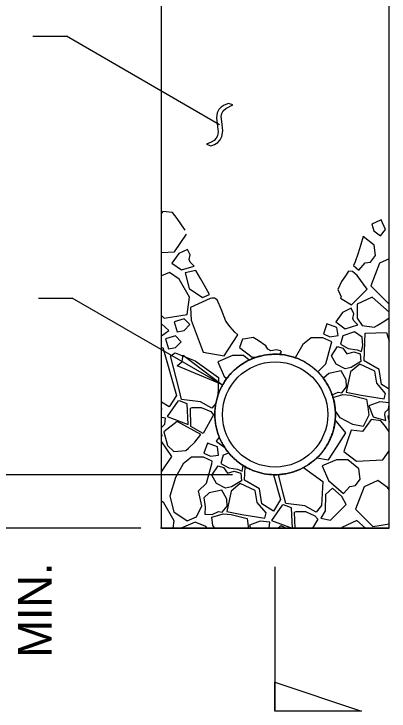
# Model space of a CAD drawing. Extents: x 99862 to 103151, y 100000 to 108153.
# Drawn here: x 100203.1 to 100381.2, y 100207.5 to 100538.8 of the extents above; entities that cross this region are included whole.
import ezdxf

# ---------------------------------------------------------------- set-up
doc = ezdxf.new("R2010")
doc.units = 0
for name, color, linetype in [('Level 10', 7, 'Continuous'), ('Level 14', 7, 'Continuous'), ('Level 15', 7, 'Continuous'), ('Level 2', 7, 'Continuous'), ('Level 20', 7, 'Continuous'), ('Level 9', 7, 'Continuous')]:
    doc.layers.add(name, color=color, linetype=linetype)

msp = doc.modelspace()

# ---------------------------------------------------------------- linework, layer by layer
at = {"layer": 'Level 10'}
for points in [[(100273.15, 100294.34), (100273.15, 100794.33)], [(100381.2, 100294.34), (100381.2, 100794.33)]]:
    msp.add_lwpolyline(points, dxfattribs=at)
at = {"layer": 'Level 14'}
msp.add_line((100329.23, 100376.99), (100330.07, 100378.22), dxfattribs=at)
for points in [[(100284.41, 100436.05), (100280.52, 100441.64), (100278.31, 100444.45), (100273.79, 100444.93), (100273.15, 100444.06)], [(100374.01, 100435.77), (100377.11, 100433.32), (100379.56, 100436.42), (100377.53, 100440.98), (100372.97, 100438.95), (100372.97, 100438.95), (100374.01, 100435.77)], [(100273.15, 100425.51), (100279.29, 100425.8), (100284.95, 100434.08)], [(100368.97, 100433.04), (100367.84, 100429.31), (100367, 100426.71), (100366.48, 100425.11), (100365.04, 100420.99), (100364.36, 100419.22)], [(100364.36, 100419.22), (100366.87, 100417.05), (100369.81, 100420.45), (100372.46, 100420.83), (100374.76, 100423.95), (100374.1, 100428.87), (100368.97, 100433.04)], [(100381.2, 100422.36), (100376.6, 100420.29), (100372.5, 100409.62), (100380.71, 100401.4), (100381.2, 100401.48)], [(100273.15, 100395.48), (100274.49, 100394.14), (100278.43, 100394.79), (100285.28, 100395.94), (100286.48, 100404.16), (100281.55, 100412.7), (100276.95, 100415.98), (100273.15, 100414.27)], [(100295.98, 100405.42), (100293.49, 100409.8), (100291.64, 100413.07), (100289.47, 100416.9), (100284.37, 100415.79), (100286.26, 100408.31), (100292.67, 100404.04), (100295.88, 100405.44)], [(100363.78, 100416.38), (100361.91, 100416.6), (100360.23, 100413.93), (100358.55, 100411.59), (100356.86, 100407.8), (100358.43, 100404.31), (100358.09, 100403.66)], [(100358.09, 100403.66), (100363.38, 100400.52), (100370.75, 100407.97), (100366.06, 100414.44), (100363.78, 100416.38)], [(100297.07, 100403.75), (100296.33, 100403.5), (100286.89, 100399.31), (100287.22, 100393.23), (100292.88, 100378.04), (100302.98, 100376.32), (100307.09, 100382.72), (100309.37, 100386.27)], [(100309.37, 100386.27), (100307.99, 100387.61), (100305.79, 100390.07), (100303.65, 100392.76), (100301.57, 100398.15), (100299.57, 100402.87), (100298.39, 100403.77), (100297.07, 100403.75)], [(100381.2, 100397.11), (100373.2, 100404.2), (100366.03, 100400.88), (100366.1, 100394.16), (100368.47, 100390.78), (100374.18, 100389.95), (100375.57, 100390.68), (100379.13, 100392.88), (100381.2, 100394.43)], [(100283.85, 100388.39), (100286.64, 100391.18), (100283.85, 100393.97), (100279.09, 100392.5), (100280.57, 100387.73), (100280.57, 100387.73), (100283.85, 100388.39)], [(100273.15, 100385.8), (100276.61, 100388.39), (100273.15, 100391.46)], [(100353.11, 100385.33), (100357.01, 100385.91), (100356.43, 100389.82), (100351.73, 100391.47), (100350.08, 100386.77), (100350.08, 100386.77), (100353.11, 100385.33)], [(100279.76, 100380.23), (100282.55, 100383.03), (100279.76, 100385.82), (100275, 100384.34), (100276.48, 100379.58), (100276.48, 100379.58), (100279.76, 100380.23)], [(100381.2, 100360.44), (100377.58, 100362.74), (100376.43, 100369.8), (100369.37, 100373.9), (100369.82, 100387.14), (100380, 100387.47), (100381.2, 100383.26)], [(100311.58, 100384.3), (100310.21, 100380.26), (100316.21, 100375.74), (100318.92, 100375.87)], [(100330.07, 100378.22), (100329.58, 100378.75), (100327.77, 100379.1), (100325.13, 100378.75), (100323.64, 100379.44), (100322.74, 100381.11), (100319.11, 100383.59), (100316.72, 100384.96), (100313.06, 100384.37), (100311.58, 100384.3)], [(100354.02, 100383.03), (100349.83, 100384.82), (100344.2, 100384.87), (100340.26, 100381.75), (100336.63, 100375.44)], [(100347.6, 100368.44), (100347.48, 100368.94), (100351.26, 100372.55), (100353.74, 100381.79), (100354.02, 100383.03)], [(100273.15, 100380.18), (100273.78, 100380.2), (100280.23, 100357.44), (100276.78, 100352.02), (100273.15, 100354.33)], [(100298.97, 100353.71), (100297.08, 100351.43), (100291.68, 100354.48), (100282.69, 100355.63), (100281.33, 100361.01), (100277.44, 100376.35), (100279.64, 100377.68), (100289.2, 100373.99), (100300.26, 100365.98), (100299.82, 100357.07)], [(100314.74, 100374.25), (100312.1, 100376.4), (100306.84, 100376.4), (100299.95, 100373.44), (100302.9, 100366.55), (100304.12, 100365.49)], [(100318.92, 100375.87), (100319.63, 100376.07), (100320.74, 100376.35), (100321.87, 100376.58), (100323.02, 100376.78), (100324.2, 100376.92), (100325.41, 100377.02), (100326.63, 100377.06), (100327.86, 100377.06), (100329.11, 100377), (100329.23, 100376.99)], [(100304.12, 100365.49), (100304.62, 100366.15), (100305.36, 100367.05), (100306.13, 100367.92), (100306.92, 100368.73), (100307.73, 100369.51), (100308.55, 100370.24), (100309.39, 100370.92), (100310.23, 100371.56), (100311.08, 100372.16), (100311.94, 100372.72), (100312.8, 100373.23), (100313.67, 100373.72), (100314.58, 100374.18), (100314.74, 100374.25)], [(100354.2, 100357.7), (100356.97, 100359.12), (100358.73, 100358.75), (100361.07, 100361.59), (100360.87, 100364.91), (100358.53, 100369.14), (100352.53, 100367.91), (100350.01, 100365.63)], [(100350.01, 100365.63), (100350.13, 100365.47), (100350.85, 100364.44), (100351.53, 100363.39), (100352.15, 100362.33), (100352.72, 100361.25), (100353.24, 100360.16), (100353.7, 100359.06), (100354.11, 100357.97), (100354.2, 100357.7)], [(100299.82, 100357.07), (100299.56, 100356.22), (100299.24, 100354.96), (100298.97, 100353.71)], [(100354.56, 100356.57), (100359.25, 100357.89), (100362.94, 100357.64), (100370.5, 100355.67), (100371.07, 100351.9), (100371.65, 100348.12), (100368.85, 100342.78), (100363.93, 100343.6), (100357.93, 100346.89), (100355.68, 100350.37)], [(100355.68, 100350.37), (100355.68, 100350.46), (100355.58, 100351.5), (100355.45, 100352.55), (100355.27, 100353.61), (100355.06, 100354.69), (100354.79, 100355.78), (100354.56, 100356.57)], [(100381.2, 100354), (100376.79, 100354.49), (100371.61, 100352.51), (100373.58, 100347.33), (100379.65, 100345.61), (100379.12, 100348.2), (100379.41, 100349.47), (100380.97, 100351.03), (100381.2, 100353.09)], [(100273.15, 100350.38), (100273.35, 100351.16), (100273.15, 100351.39)], [(100287.67, 100351.76), (100292.03, 100351.73), (100296.54, 100349.79), (100297.92, 100348.22), (100292.92, 100339.45), (100287.11, 100342.69), (100286.85, 100351.44), (100287.67, 100351.76)], [(100273.15, 100342.04), (100273.19, 100342.21), (100274.75, 100343.77), (100275.07, 100346.72), (100273.15, 100346.94)], [(100355.63, 100345.96), (100355.58, 100345.38), (100355.45, 100344.33), (100355.27, 100343.26), (100355.06, 100342.18), (100354.79, 100341.1), (100354.48, 100340), (100354.11, 100338.91), (100353.7, 100337.81), (100353.24, 100336.71), (100352.72, 100335.63), (100352.15, 100334.55), (100351.53, 100333.48), (100350.85, 100332.43), (100350.13, 100331.4), (100349.35, 100330.39), (100348.51, 100329.41), (100347.63, 100328.47), (100346.94, 100327.78)], [(100346.94, 100327.78), (100352.46, 100326.84), (100356.57, 100333.25), (100360.67, 100339.65), (100355.63, 100345.96)], [(100381.2, 100340.21), (100379.48, 100342.69), (100377.26, 100345.49), (100372.74, 100345.97), (100368.56, 100340.31), (100363.14, 100340.96), (100359.69, 100330.78), (100365.68, 100326.27), (100378.25, 100326.84), (100381.2, 100331.15)], [(100381.2, 100347.92), (100380.56, 100347.42), (100381.2, 100344.82)], [(100273.15, 100338.43), (100273.43, 100338.35), (100273.15, 100339.72)], [(100300.58, 100337.7), (100299.11, 100335.71), (100303.19, 100332.72)], [(100303.19, 100332.72), (100302.57, 100333.7), (100301.95, 100334.77), (100301.38, 100335.88), (100300.85, 100337.03), (100300.58, 100337.7)], [(100273.15, 100321.22), (100278.09, 100328.45), (100273.26, 100335.42), (100273.15, 100335.56)], [(100296.36, 100328.59), (100300.27, 100329.17), (100299.69, 100333.07), (100294.99, 100334.73), (100293.33, 100330.02), (100293.33, 100330.02), (100296.36, 100328.59)], [(100305.17, 100330.06), (100302.44, 100329.15), (100301.37, 100325.13), (100305.07, 100323.07), (100309.26, 100322.5), (100311.43, 100321.55), (100311.9, 100324.18)], [(100311.9, 100324.18), (100311.08, 100324.71), (100310.23, 100325.31), (100309.39, 100325.95), (100308.55, 100326.64), (100307.73, 100327.37), (100306.92, 100328.14), (100306.13, 100328.96), (100305.36, 100329.82), (100305.17, 100330.06)], [(100297.27, 100326.28), (100293.09, 100328.07), (100287.45, 100328.12), (100283.51, 100325), (100279.74, 100318.43), (100277.11, 100309.56), (100279, 100302.09), (100285.4, 100297.82), (100289.75, 100299.71), (100292.38, 100304.97), (100290.74, 100312.19), (100294.52, 100315.81), (100297, 100325.04), (100297.27, 100326.28)], [(100326.35, 100319.82), (100329.7, 100307.96), (100326.26, 100302.54), (100320.84, 100305.99), (100319.69, 100313.05), (100312.62, 100317.16), (100312.84, 100323.61)], [(100312.84, 100323.61), (100313.67, 100323.15), (100314.58, 100322.69), (100315.53, 100322.25), (100316.51, 100321.84), (100317.52, 100321.46), (100318.56, 100321.11), (100319.63, 100320.8), (100320.74, 100320.52), (100321.87, 100320.29), (100323.02, 100320.1), (100324.2, 100319.95), (100325.41, 100319.86), (100326.35, 100319.82)], [(100328.7, 100319.85), (100329.11, 100319.87), (100330.36, 100319.99), (100331.63, 100320.16), (100332.89, 100320.39), (100334.15, 100320.68), (100335.4, 100321.03), (100336.65, 100321.44), (100337.87, 100321.9), (100339.08, 100322.43), (100340.27, 100323.01), (100340.55, 100323.16)], [(100340.55, 100323.16), (100349.74, 100316.5), (100349.18, 100305.11), (100346.56, 100301.95), (100341.15, 100305), (100332.17, 100306.16), (100330.8, 100311.54), (100328.7, 100319.85)], [(100381.2, 100312.55), (100380.51, 100313.74), (100375.91, 100317.03), (100369.34, 100314.07), (100365.23, 100303.39), (100373.44, 100295.18), (100377.39, 100295.84), (100381.2, 100296.47)], [(100278.69, 100294.34), (100279.21, 100297.93), (100274.29, 100306.47), (100273.15, 100307.29)], [(100335.37, 100294.34), (100334.8, 100304.02), (100331.1, 100305.42), (100331.1, 100305.42), (100330.44, 100305.25), (100325.35, 100298.03), (100335.12, 100294.34)], [(100298.47, 100294.34), (100297.58, 100295.73), (100297.12, 100299.63), (100302.5, 100301.15), (100306.2, 100300.9), (100313.75, 100298.93), (100314.33, 100295.15), (100314.45, 100294.34)], [(100336.56, 100294.34), (100336.33, 100301.96), (100337.15, 100302.29)], [(100337.15, 100302.29), (100341.51, 100302.26), (100346.02, 100300.32), (100347.4, 100298.75), (100344.89, 100294.34)], [(100294.8, 100294.34), (100294.16, 100295.14), (100289.07, 100297.28), (100282.45, 100294.34)], [(100324.23, 100294.34), (100324.55, 100297.25), (100320.05, 100297.75), (100314.86, 100295.77), (100315.41, 100294.34)], [(100370.03, 100294.34), (100365.93, 100297.98), (100358.76, 100294.66), (100358.77, 100294.34)], [(100332.26, 100294.34), (100330.03, 100295.54), (100328.5, 100294.34)], [(100381.2, 100294.52), (100380.63, 100294.34)]]:
    msp.add_lwpolyline(points, dxfattribs=at)
for points in [[(100286.3, 100422.1), (100286.77, 100424.26), (100285.44, 100426.92), (100281.38, 100424.9), (100278.09, 100420.43), (100282.57, 100417.15), (100288.6, 100418.99), (100286.75, 100420.88)], [(100364.06, 100394.12), (100364.53, 100396.28), (100363.2, 100398.94), (100359.14, 100396.92), (100355.86, 100392.45), (100360.33, 100389.17), (100366.36, 100391.01), (100364.51, 100392.9)], [(100366, 100379.24), (100368.18, 100378.3), (100368.71, 100381.29), (100368.46, 100385.24), (100364.85, 100387.78), (100359.19, 100385.89), (100358.12, 100381.87), (100361.81, 100379.82)], [(100364.4, 100378.22), (100367.56, 100377.27), (100367.81, 100373.58), (100363.17, 100370.82), (100360.29, 100370.17), (100356.02, 100372.38), (100353.81, 100376.33), (100356.72, 100380.8), (100359.27, 100379.98), (100361.2, 100377.23)], [(100374.44, 100369.06), (100367.29, 100372.43), (100362.94, 100368.73), (100360.89, 100359.12), (100367.98, 100357.61), (100378.91, 100355.88), (100379.57, 100358.42), (100375.36, 100363.29)], [(100280.97, 100354.73), (100275.87, 100347.5), (100285.89, 100343.73), (100285.32, 100353.5), (100281.62, 100354.9), (100281.62, 100354.9)], [(100285.95, 100332.39), (100288.91, 100335.35), (100291.89, 100338.9), (100280.56, 100345.02), (100274.33, 100340.15), (100275.94, 100333.63), (100279.02, 100330.88), (100284.76, 100331.37)], [(100367.49, 100317.73), (100366.83, 100322.65), (100361.58, 100326.92), (100356.32, 100326.92), (100349.42, 100323.97), (100352.38, 100317.07), (100359.61, 100310.83), (100362.55, 100314.23), (100365.19, 100314.6)], [(100307.66, 100321.47), (100310.82, 100320.53), (100311.06, 100316.83), (100306.42, 100314.08), (100303.55, 100313.42), (100299.28, 100315.64), (100297.06, 100319.58), (100299.98, 100324.06), (100302.52, 100323.24), (100304.45, 100320.49)], [(100317.69, 100312.32), (100310.55, 100315.68), (100306.2, 100311.99), (100304.15, 100302.38), (100311.23, 100300.86), (100322.17, 100299.14), (100322.83, 100301.68), (100318.62, 100306.55)], [(100360.84, 100305.65), (100358.79, 100309.51), (100354.29, 100313.35), (100350.98, 100310.42), (100350.94, 100302.58), (100348.87, 100299.13), (100353.47, 100298.21)], [(100300.22, 100302.38), (100301.99, 100302.01), (100304.33, 100304.84), (100304.12, 100308.17), (100301.78, 100312.4), (100295.79, 100311.17), (100293.24, 100308.87), (100293.82, 100304.51), (100293.65, 100300.98), (100297.19, 100300.82)]]:
    msp.add_lwpolyline(points, close=True, dxfattribs=at)
at = {"layer": 'Level 15'}
for p, q in [((100211.99, 100528.2), (100227.99, 100528.2)), ((100300.74, 100486.19), (100227.99, 100528.2)), ((100302.95, 100495.49), (100301.45, 100494.54)), ((100304.96, 100496.25), (100302.95, 100495.49)), ((100303.65, 100493.91), (100306.96, 100495.57)), ((100306.96, 100495.57), (100304.96, 100496.25)), ((100299.63, 100491.85), (100299.2, 100489.42)), ((100300.36, 100493.34), (100299.63, 100491.85)), ((100301.45, 100494.54), (100300.36, 100493.34)), ((100301.76, 100491.55), (100302.45, 100492.79)), ((100302.45, 100492.79), (100303.65, 100493.91)), ((100299.2, 100489.42), (100299.72, 100485.37)), ((100301.51, 100490.07), (100301.76, 100491.55)), ((100301.77, 100487.66), (100301.51, 100490.07)), ((100299.72, 100485.37), (100299.99, 100482.83)), ((100302.26, 100483.27), (100301.77, 100487.66)), ((100299.99, 100482.83), (100299.72, 100480.93)), ((100301.84, 100480.59), (100302.26, 100483.27)), ((100298.2, 100478.74), (100296.73, 100477.82)), ((100299.12, 100479.74), (100298.2, 100478.74)), ((100299.72, 100480.93), (100299.12, 100479.74)), ((100299.91, 100477.74), (100301.06, 100479.01)), ((100301.06, 100479.01), (100301.84, 100480.59)), ((100296.73, 100477.82), (100294.5, 100476.85)), ((100294.5, 100476.85), (100296.5, 100476.17)), ((100296.5, 100476.17), (100298.39, 100476.8)), ((100298.39, 100476.8), (100299.91, 100477.74)), ((100214.79, 100403.65), (100230.79, 100403.65)), ((100301.79, 100362.66), (100230.79, 100403.65))]:
    msp.add_line(p, q, dxfattribs=at)
msp.add_lwpolyline([(100301.79, 100362.66), (100280.53, 100371.49), (100282.93, 100373.55), (100283.51, 100376.66)], close=True, dxfattribs=at)
for points in [[(100306.89, 100319.8), (100180.49, 100319.8)], [(100263.32, 100294.34), (100179.86, 100294.34)]]:
    msp.add_lwpolyline(points, dxfattribs=at)
at = {"layer": 'Level 2'}
msp.add_line((100273.15, 100294.34), (100381.2, 100294.34), dxfattribs=at)
at = {"layer": 'Level 20'}
for points in [[(100273.15, 100294.34), (100273.15, 100463.37)], [(100381.2, 100294.34), (100381.2, 100463.37)], [(100317.52, 100375.41), (100318.56, 100375.76)], [(100318.56, 100375.76), (100319.63, 100376.07)], [(100319.63, 100376.07), (100320.74, 100376.35)], [(100320.74, 100376.35), (100321.87, 100376.58)], [(100321.87, 100376.58), (100323.02, 100376.78)], [(100323.02, 100376.78), (100324.2, 100376.92)], [(100324.2, 100376.92), (100325.41, 100377.02)], [(100325.41, 100377.02), (100326.63, 100377.06)], [(100326.63, 100377.06), (100327.86, 100377.06)], [(100327.86, 100377.06), (100329.11, 100377)], [(100329.11, 100377), (100330.36, 100376.88)], [(100330.36, 100376.88), (100331.63, 100376.71)], [(100331.63, 100376.71), (100332.89, 100376.48)], [(100332.89, 100376.48), (100334.15, 100376.19)], [(100334.15, 100376.19), (100335.4, 100375.84)], [(100335.4, 100375.84), (100336.65, 100375.44)], [(100311.08, 100372.16), (100311.94, 100372.72)], [(100311.94, 100372.72), (100312.8, 100373.23)], [(100312.8, 100373.23), (100313.67, 100373.72)], [(100313.67, 100373.72), (100314.58, 100374.18)], [(100314.58, 100374.18), (100315.53, 100374.62)], [(100315.53, 100374.62), (100316.51, 100375.03)], [(100316.51, 100375.03), (100317.52, 100375.41)], [(100336.65, 100375.44), (100337.87, 100374.97)], [(100337.87, 100374.97), (100339.08, 100374.45)], [(100339.08, 100374.45), (100340.27, 100373.87)], [(100340.27, 100373.87), (100341.43, 100373.23)], [(100341.43, 100373.23), (100342.56, 100372.55)], [(100342.56, 100372.55), (100343.66, 100371.81)], [(100306.92, 100368.73), (100307.73, 100369.51)], [(100307.73, 100369.51), (100308.55, 100370.24)], [(100308.55, 100370.24), (100309.39, 100370.92)], [(100309.39, 100370.92), (100310.23, 100371.56)], [(100310.23, 100371.56), (100311.08, 100372.16)], [(100343.66, 100371.81), (100344.71, 100371.02)], [(100344.71, 100371.02), (100345.73, 100370.19)], [(100345.73, 100370.19), (100346.71, 100369.32)], [(100346.71, 100369.32), (100347.63, 100368.41)], [(100303.9, 100365.2), (100304.62, 100366.15)], [(100304.62, 100366.15), (100305.36, 100367.05)], [(100305.36, 100367.05), (100306.13, 100367.92)], [(100306.13, 100367.92), (100306.92, 100368.73)], [(100347.63, 100368.41), (100348.51, 100367.46)], [(100348.51, 100367.46), (100349.35, 100366.48)], [(100349.35, 100366.48), (100350.13, 100365.47)], [(100301.95, 100362.1), (100302.57, 100363.17)], [(100302.57, 100363.17), (100303.22, 100364.21)], [(100303.22, 100364.21), (100303.9, 100365.2)], [(100350.13, 100365.47), (100350.85, 100364.44)], [(100350.85, 100364.44), (100351.53, 100363.39)], [(100351.53, 100363.39), (100352.15, 100362.33)], [(100300.37, 100358.67), (100300.85, 100359.85)], [(100300.85, 100359.85), (100301.38, 100360.99)], [(100301.38, 100360.99), (100301.95, 100362.1)], [(100352.15, 100362.33), (100352.72, 100361.25)], [(100352.72, 100361.25), (100353.24, 100360.16)], [(100353.24, 100360.16), (100353.7, 100359.06)], [(100353.7, 100359.06), (100354.11, 100357.97)], [(100299.24, 100354.96), (100299.56, 100356.22)], [(100299.56, 100356.22), (100299.94, 100357.46)], [(100299.94, 100357.46), (100300.37, 100358.67)], [(100354.11, 100357.97), (100354.48, 100356.87)], [(100354.48, 100356.87), (100354.79, 100355.78)], [(100354.79, 100355.78), (100355.06, 100354.69)], [(100298.76, 100352.39), (100298.97, 100353.68)], [(100298.97, 100353.68), (100299.24, 100354.96)], [(100355.06, 100354.69), (100355.27, 100353.61)], [(100355.27, 100353.61), (100355.45, 100352.55)], [(100355.45, 100352.55), (100355.58, 100351.5)], [(100298.48, 100348.44), (100298.51, 100349.76)], [(100298.51, 100349.76), (100298.6, 100351.08)], [(100298.6, 100351.08), (100298.76, 100352.39)], [(100355.58, 100351.5), (100355.68, 100350.46)], [(100355.68, 100350.46), (100355.73, 100349.44)], [(100355.73, 100349.44), (100355.75, 100348.44)], [(100298.51, 100347.11), (100298.48, 100348.44)], [(100298.6, 100345.8), (100298.51, 100347.11)], [(100355.68, 100346.42), (100355.58, 100345.38)], [(100355.73, 100347.44), (100355.68, 100346.42)], [(100355.75, 100348.44), (100355.73, 100347.44)], [(100298.76, 100344.49), (100298.6, 100345.8)], [(100298.97, 100343.19), (100298.76, 100344.49)], [(100299.24, 100341.91), (100298.97, 100343.19)], [(100355.27, 100343.26), (100355.06, 100342.18)], [(100355.45, 100344.33), (100355.27, 100343.26)], [(100355.58, 100345.38), (100355.45, 100344.33)], [(100299.56, 100340.65), (100299.24, 100341.91)], [(100299.94, 100339.42), (100299.56, 100340.65)], [(100300.37, 100338.21), (100299.94, 100339.42)], [(100354.48, 100340), (100354.11, 100338.91)], [(100354.79, 100341.1), (100354.48, 100340)], [(100355.06, 100342.18), (100354.79, 100341.1)], [(100300.85, 100337.03), (100300.37, 100338.21)], [(100301.38, 100335.88), (100300.85, 100337.03)], [(100301.95, 100334.77), (100301.38, 100335.88)], [(100353.24, 100336.71), (100352.72, 100335.63)], [(100353.7, 100337.81), (100353.24, 100336.71)], [(100354.11, 100338.91), (100353.7, 100337.81)], [(100302.57, 100333.7), (100301.95, 100334.77)], [(100303.22, 100332.67), (100302.57, 100333.7)], [(100303.9, 100331.67), (100303.22, 100332.67)], [(100351.53, 100333.48), (100350.85, 100332.43)], [(100352.15, 100334.55), (100351.53, 100333.48)], [(100352.72, 100335.63), (100352.15, 100334.55)], [(100304.62, 100330.72), (100303.9, 100331.67)], [(100305.36, 100329.82), (100304.62, 100330.72)], [(100306.13, 100328.96), (100305.36, 100329.82)], [(100348.51, 100329.41), (100347.63, 100328.47)], [(100349.35, 100330.39), (100348.51, 100329.41)], [(100350.13, 100331.4), (100349.35, 100330.39)], [(100350.85, 100332.43), (100350.13, 100331.4)], [(100306.92, 100328.14), (100306.13, 100328.96)], [(100307.73, 100327.37), (100306.92, 100328.14)], [(100308.55, 100326.64), (100307.73, 100327.37)], [(100309.39, 100325.95), (100308.55, 100326.64)], [(100310.23, 100325.31), (100309.39, 100325.95)], [(100345.73, 100326.68), (100344.71, 100325.85)], [(100346.71, 100327.56), (100345.73, 100326.68)], [(100347.63, 100328.47), (100346.71, 100327.56)], [(100311.08, 100324.71), (100310.23, 100325.31)], [(100311.94, 100324.16), (100311.08, 100324.71)], [(100312.8, 100323.64), (100311.94, 100324.16)], [(100313.67, 100323.15), (100312.8, 100323.64)], [(100314.58, 100322.69), (100313.67, 100323.15)], [(100315.53, 100322.25), (100314.58, 100322.69)], [(100340.27, 100323.01), (100339.08, 100322.43)], [(100341.43, 100323.64), (100340.27, 100323.01)], [(100342.56, 100324.33), (100341.43, 100323.64)], [(100343.66, 100325.07), (100342.56, 100324.33)], [(100344.71, 100325.85), (100343.66, 100325.07)], [(100316.51, 100321.84), (100315.53, 100322.25)], [(100317.52, 100321.46), (100316.51, 100321.84)], [(100318.56, 100321.11), (100317.52, 100321.46)], [(100319.63, 100320.8), (100318.56, 100321.11)], [(100320.74, 100320.52), (100319.63, 100320.8)], [(100321.87, 100320.29), (100320.74, 100320.52)], [(100323.02, 100320.1), (100321.87, 100320.29)], [(100324.2, 100319.95), (100323.02, 100320.1)], [(100325.41, 100319.86), (100324.2, 100319.95)], [(100326.63, 100319.81), (100325.41, 100319.86)], [(100327.86, 100319.81), (100326.63, 100319.81)], [(100329.11, 100319.87), (100327.86, 100319.81)], [(100330.36, 100319.99), (100329.11, 100319.87)], [(100331.63, 100320.16), (100330.36, 100319.99)], [(100332.89, 100320.39), (100331.63, 100320.16)], [(100334.15, 100320.68), (100332.89, 100320.39)], [(100335.4, 100321.03), (100334.15, 100320.68)], [(100336.65, 100321.44), (100335.4, 100321.03)], [(100337.87, 100321.9), (100336.65, 100321.44)], [(100339.08, 100322.43), (100337.87, 100321.9)], [(100381.2, 100294.34), (100272.7, 100294.34)]]:
    msp.add_lwpolyline(points, dxfattribs=at)
msp.add_circle((100327.11, 100348.44), 24.99, dxfattribs=at)
for start, end in [(107.3824, 109.5826), (105.1445, 107.3824), (102.8698, 105.1445), (100.559, 102.8698), (98.2132, 100.559), (95.8337, 98.2132), (93.4218, 95.8337), (90.9791, 93.4218), (88.5072, 90.9791), (86.0078, 88.5072), (83.4831, 86.0078), (80.935, 83.4831), (78.3658, 80.935), (75.7778, 78.3658), (73.1736, 75.7778), (70.5556, 73.1736), (122.0046, 124.0489), (120, 122.0046), (117.9954, 120), (115.9511, 117.9954), (113.8674, 115.9511), (111.7444, 113.8674), (109.5826, 111.7444), (67.9265, 70.5556), (65.289, 67.9265), (62.6459, 65.289), (60, 62.6459), (57.3541, 60), (54.711, 57.3541), (132.6176, 134.8555), (130.4174, 132.6176), (128.2556, 130.4174), (126.1326, 128.2556), (124.0489, 126.1326), (52.0735, 54.711), (49.4444, 52.0735), (46.8264, 49.4444), (44.2222, 46.8264), (141.7868, 144.1663), (139.441, 141.7868), (137.1302, 139.441), (134.8555, 137.1302), (41.6342, 44.2222), (39.065, 41.6342), (36.5169, 39.065), (149.0209, 151.4928), (146.5782, 149.0209), (144.1663, 146.5782), (33.9922, 36.5169), (31.4928, 33.9922), (29.0209, 31.4928), (156.5169, 159.065), (153.9922, 156.5169), (151.4928, 153.9922), (26.5782, 29.0209), (24.1663, 26.5782), (21.7868, 24.1663), (19.441, 21.7868), (164.2222, 166.8264), (161.6342, 164.2222), (159.065, 161.6342), (17.1302, 19.441), (14.8555, 17.1302), (12.6176, 14.8555), (169.4444, 172.0735), (166.8264, 169.4444), (10.4174, 12.6176), (8.2556, 10.4174), (6.1326, 8.2556), (177.3541, 180), (174.711, 177.3541), (172.0735, 174.711), (4.0489, 6.1326), (2.0046, 4.0489), (0, 2.0046), (180, 182.6459), (182.6459, 185.289), (353.8674, 355.9511), (355.9511, 357.9954), (357.9954, 360), (185.289, 187.9265), (187.9265, 190.5556), (190.5556, 193.1736), (347.3824, 349.5826), (349.5826, 351.7444), (351.7444, 353.8674), (193.1736, 195.7778), (195.7778, 198.3658), (198.3658, 200.935), (340.559, 342.8698), (342.8698, 345.1445), (345.1445, 347.3824), (200.935, 203.4831), (203.4831, 206.0078), (206.0078, 208.5072), (333.4218, 335.8337), (335.8337, 338.2132), (338.2132, 340.559), (208.5072, 210.9791), (210.9791, 213.4218), (213.4218, 215.8337), (326.0078, 328.5072), (328.5072, 330.9791), (330.9791, 333.4218), (215.8337, 218.2132), (218.2132, 220.559), (220.559, 222.8698), (315.7778, 318.3658), (318.3658, 320.935), (320.935, 323.4831), (323.4831, 326.0078), (222.8698, 225.1445), (225.1445, 227.3824), (227.3824, 229.5826), (229.5826, 231.7444), (231.7444, 233.8674), (307.9265, 310.5556), (310.5556, 313.1736), (313.1736, 315.7778), (233.8674, 235.9511), (235.9511, 237.9954), (237.9954, 240), (240, 242.0046), (242.0046, 244.0489), (244.0489, 246.1326), (294.711, 297.3541), (297.3541, 300), (300, 302.6459), (302.6459, 305.289), (305.289, 307.9265), (246.1326, 248.2556), (248.2556, 250.4174), (250.4174, 252.6176), (252.6176, 254.8555), (254.8555, 257.1302), (257.1302, 259.441), (259.441, 261.7868), (261.7868, 264.1663), (264.1663, 266.5782), (266.5782, 269.0209), (269.0209, 271.4928), (271.4928, 273.9922), (273.9922, 276.5169), (276.5169, 279.065), (279.065, 281.6342), (281.6342, 284.2222), (284.2222, 286.8264), (286.8264, 289.4444), (289.4444, 292.0735), (292.0735, 294.711)]:
    msp.add_arc((100327.11, 100348.44), 28.63, start, end, dxfattribs=at)
at = {"layer": 'Level 9'}
msp.add_line((100326.9, 100276.01), (100326.9, 100208.09), dxfattribs=at)
msp.add_lwpolyline([(100326.9, 100221.12), (100368.16, 100207.46), (100326.9, 100207.46)], close=True, dxfattribs=at)

# ---------------------------------------------------------------- texts
at = {"layer": 'Level 20'}
msp.add_text('MIN.', height=16, rotation=90, dxfattribs=at).set_placement((100221.07, 100232.88))

doc.saveas('drawing.dxf')
